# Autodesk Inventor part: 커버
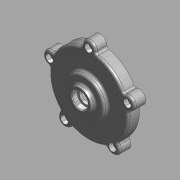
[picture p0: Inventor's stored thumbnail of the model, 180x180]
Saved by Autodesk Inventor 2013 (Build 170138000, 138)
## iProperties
Created: 2015-11
Part Number: 커버
Document SubType Name: 모델링
Designer: mdu
Material: 알루미늄 6061
Density: 1 g/cm^3
변환 표준: STEP AP214IS
파일 이름: C:\Users\SeoGD\Desktop\?쒗뿕\而ㅻ쾭-1.stp
전처리기: Build: 253, Release: 2010 SP1 - Date: Wed 07/29/2009
전송 단위: 밀리미터
불확실성: 0.01
Author: mdu
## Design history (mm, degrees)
sketch "스케치1"
  geometry: L1 (0, 0)-(0, 26); L2 (50, 0)-(50, 15); L3 (50, 15)-(25, 15); L4 (25, 15)-(25, 21); L5 (25, 21)-(15, 21); L6 (15, 21)-(13.66, 26); L7 (13.66, 26)-(10, 26); L8 (50, 0)-(45, 0); L9 (45, 0)-(45, 10); L10 (45, 10)-(14.5, 10); L11 (14.5, 10)-(13.266, 3); L12 (13.266, 3)-(11, 3); L13 (11, 3)-(11, 16); L14 (11, 16)-(7.5, 16); L15 (7.5, 16)-(7.5, 19); L16 (7.5, 19)-(10, 19); L17 (10, 19)-(10, 26)
  constraints: 34 end point, 10 parallel, 2 perpendicular, 2 point on line, 1 vertical
  dimensions: "d11" = 100 diameter of L2 L1; "d12" = 22 diameter of L13 L1; "d13" = 90 diameter of L9 L1; "d14" = 15 distance between parallel lines of L3 L8; "d15" = 10 distance between parallel lines of L8 L10; "d16" = 29 diameter of L10.end L1; "d17" = 100 deg angle of L11 L10; "d18" = 7 distance between parallel lines of L12 L10; "d19" = 13 distance between parallel lines of L14 L12; "d20" = 3 distance between parallel lines of L16 L14; "d21" = 15 diameter of L15 L1; "d22" = 20 diameter of L17 L1; "d23" = 30 diameter of L5.end L1; "d24" = 6 distance between parallel lines of L5 L3; "d25" = 50 diameter of L4 L1; "d26" = 105 deg angle of L5 L6; "d50" = 26 distance of L1.start L1.end
revolve "회전1" sketch "스케치1" stored, may be unused: angle "d27" = 90 deg
sketch "스케치2" dims "d29" = 104
  geometry: A1 r 8.5 centre (0, 52) between (8.074, 49.344) and (-8.074, 49.344); A2 r 50 centre (0, 0) between (-8.074, 49.344) and (8.074, 49.344) reference; 2 further points
  constraints: 4 point on circle, 2 vertical alignment, 1 centre point, 1 coincident, 2 other
  dimensions: "d28" = 17 diameter of A1
extrude "돌출1" join sketch "스케치2" stored distance "d30" = 10; taper "d31" = 0 deg
fillet "모깎기3" dims "d32" = 3
fillet "모깎기4" dims "d45" = 3, "d46" = 0.2
chamfer "모따기1" distance "d47" = 1; stored, may be unused: second distance "d48" = 2, angle "d49" = 45 deg
hole "구멍2" diameter "d38" = 5.5; stored, may be unused: countersink angle "d42" = 90 deg, drill point angle "d44" = 118 deg; dims "d36" = 10, "d37" = 10, "d39" = 6, "d40" = 9.5, "d41" = 5.4, "d43" = 8
node "솔리드1"
node "솔리드 본체"
node "곡면 본체"
pattern_circular "원형 패턴1" dims angle "d34" = 360 deg
pattern_circular "원형 패턴2" dims angle "d52" = 360 deg
node "솔리드2"
